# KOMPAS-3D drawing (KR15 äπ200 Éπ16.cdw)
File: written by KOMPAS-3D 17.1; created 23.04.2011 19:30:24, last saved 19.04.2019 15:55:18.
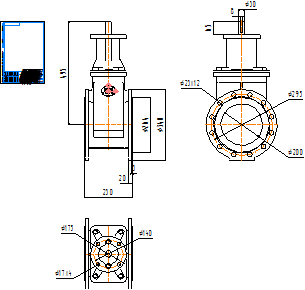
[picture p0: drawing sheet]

Sheet 1: A4, portrait

Title block, sheet 1: name: KR15 Ду200 Ру16; material: Внимание! Данный продукт является объектом авторского права ООО «Торговый Дом АДЛ». / Запрещается изменение, копирование, распространение / (в том числе путем копирования на другие сайты и ресурсы в Интернете) / или любое иное использование информации и объектов без предварительного / согласия правообладателя (ООО «Торговый Дом АДЛ»).; scale: 1:1; sheets: 1; organisation: ООО "Торговый дом АДЛ"; sheet format: A4; stored path: \\adlc.lan\data\АДЛ_ПКД\3D-модели\ADL production\Клиновые задвижки серии KR ГРАНАР\Клиновые задвижки KR15\С голым штоком\KOMPAS 2D\KR15 Ду200 Ру16.cdw

Views: Спереди 4, Проекционный вид 5, Проекционный вид 6
Dimensions and other numbers on the sheet: 230; 20; 3; 495; 340; 264; 175; 17; 140; 65; 295; 200; 23; 30; 8; 1:1; 1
